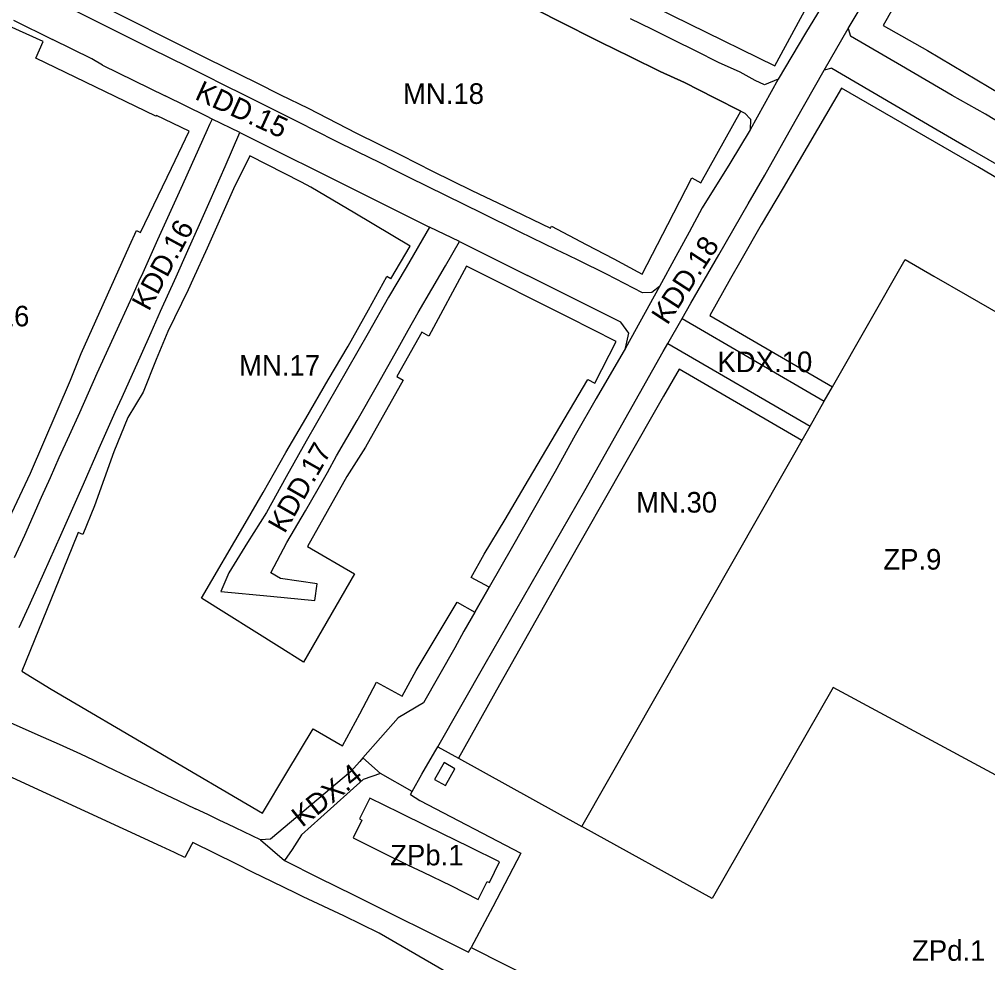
# Model space of a CAD drawing. Extents: x 7425067 to 7426806, y 5549054 to 5550619.
# Drawn here: x 7425775.6 to 7426010.9, y 5549627.2 to 5549856.3 of the extents above; entities that cross this region are included whole.
import ezdxf

# ---------------------------------------------------------------- set-up
doc = ezdxf.new("R2010")
doc.units = 0
for name, color, linetype in [('LIN_Linia Zabudowy Nieprzekraczalna', 7, 'Continuous'), ('LIN_linia zabudowy obowiązująca', 7, 'Continuous'), ('LIN_linie_rozgraniczajace', 7, 'Continuous'), ('TXT_Oznaczenia_przeznaczen', 7, 'Continuous')]:
    doc.layers.add(name, color=color, linetype=linetype)

msp = doc.modelspace()

# ---------------------------------------------------------------- linework, layer by layer
at = {"layer": 'LIN_Linia Zabudowy Nieprzekraczalna'}
for points in [[(7425801.8723, 5549907.3701), (7425781.18, 5549867.15), (7425792.69, 5549861.24), (7425821.44, 5549846.75), (7425833.18, 5549840.94), (7425839.1, 5549837.99), (7425845.79, 5549834.72), (7425857.5, 5549828.65), (7425868.39, 5549823.29), (7425875.97, 5549819.39), (7425885.52, 5549814.72), (7425893.57, 5549810.92), (7425904.63, 5549805.55), (7425904.8856, 5549806.0772)], [(7426012.3076, 5549902.588), (7426006.73, 5549891.48), (7426000.31, 5549880.37), (7425992.85, 5549867.81), (7425985.5251, 5549854.844)], [(7425845.48, 5549901.28), (7425878.63, 5549884.56), (7425896.7396, 5549875.6767), (7425959.1857, 5549845.0449)], [(7425937.19, 5549840.97), (7425931.34, 5549843.63), (7425924.075, 5549847.175), (7425916.81, 5549850.72), (7425913.24, 5549852.55), (7425909.79, 5549854.33), (7425899, 5549859.75), (7425891.99, 5549863.26), (7425886.51, 5549865.975), (7425881.03, 5549868.69), (7425872.94, 5549872.69), (7425868.2, 5549875.09), (7425863.46, 5549877.49), (7425859.61, 5549879.4), (7425855.92, 5549881.24), (7425845.49, 5549886.35), (7425841.62, 5549888.14), (7425836.88, 5549890.54), (7425827.51, 5549895.12), (7425821, 5549898.215)], [(7425959.1857, 5549845.0449), (7425974.23, 5549872.89), (7425980.2392, 5549884.0122)], [(7425779.596, 5549846.8457), (7425781.4, 5549850.92), (7425773.11, 5549854.61)], [(7425985.5251, 5549854.844), (7425996.26, 5549848.76), (7426104.12, 5549784.6), (7426109.41, 5549781.49), (7426114.72, 5549778.36), (7426119.83, 5549787.08), (7426121.57, 5549786.02), (7426124.86, 5549791.65), (7426129.1728, 5549798.7414)], [(7425816.85, 5549829.15), (7425808.9, 5549832.99), (7425808.8, 5549832.79), (7425798.91, 5549837.55), (7425779.596, 5549846.8457)], [(7425950.9226, 5549834.0102), (7425944.53, 5549837.25), (7425937.19, 5549840.97)], [(7425975.3407, 5549839.5758), (7425961.22, 5549815.39)], [(7426104.0355, 5549764.0477), (7426079.76, 5549778.72), (7426056.48, 5549792.16), (7426008.48, 5549820.45), (7425975.3407, 5549839.5758)], [(7425939.0202, 5549817.8337), (7425941.21, 5549816.62), (7425950.9226, 5549834.0102)], [(7425805.0375, 5549804.5658), (7425812.54, 5549820.18), (7425816.85, 5549829.15)], [(7425831.65, 5549823.14), (7425827.62, 5549815.16), (7425821.28, 5549800.69), (7425817.79, 5549793.15), (7425816.65, 5549790.6), (7425811.68, 5549780.51), (7425808.85, 5549773.71), (7425805.72, 5549765.73), (7425802, 5549759.61), (7425798.55, 5549751.25), (7425793.85, 5549738.13), (7425791.05, 5549731.22), (7425789.9, 5549731.68), (7425788.36, 5549727.88), (7425776.2423, 5549697.9792)], [(7425846.4612, 5549815.539), (7425844.16, 5549816.72), (7425831.65, 5549823.14)], [(7425926.9746, 5549794.4551), (7425933.16, 5549806.46), (7425939.0202, 5549817.8337)], [(7425870.6, 5549801.21), (7425857.14, 5549809.2), (7425846.4612, 5549815.539)], [(7425961.22, 5549815.39), (7425955.8554, 5549806.3779), (7425950.9113, 5549797.7633), (7425948.4236, 5549793.3414)], [(7425790.61, 5549775.16), (7425802.37, 5549801.26), (7425804.053, 5549804.9953)], [(7425804.053, 5549804.9953), (7425805.0375, 5549804.5658)], [(7425904.8856, 5549806.0772), (7425913.3, 5549801.65), (7425920.08, 5549798.1), (7425925.92, 5549795.01), (7425926.9746, 5549794.4551)], [(7425865.9, 5549793.29), (7425870.6, 5549801.21)], [(7425862.3827, 5549695.3324), (7425868.66, 5549691.91), (7425872.06, 5549698.16), (7425881.9787, 5549714.7182), (7425886.2468, 5549712.3147), (7425889.7427, 5549718.364), (7425885.4, 5549720.72), (7425888.56, 5549726.41), (7425893.62, 5549734.81), (7425899.34, 5549744.46), (7425913.7682, 5549768.8012), (7425915.44, 5549767.95), (7425920.59, 5549778.05), (7425909.13, 5549783.88), (7425884.29, 5549796.38), (7425875.1185, 5549779.3888), (7425873.44, 5549780.35), (7425867.32, 5549769.53), (7425868.8363, 5549768.6578)], [(7425819.8779, 5549715.7686), (7425830.51, 5549733.9), (7425834.85, 5549741.36), (7425840.32, 5549751.1), (7425845.18, 5549759.39), (7425850.65, 5549768.79), (7425855.51, 5549776.91), (7425860.42, 5549785.78), (7425864.9043, 5549793.881)], [(7425865.9, 5549793.29), (7425864.9043, 5549793.881)], [(7425948.4236, 5549793.3414), (7425943.4128, 5549784.38)], [(7425943.4128, 5549784.38), (7425973.1723, 5549767.0611), (7425973.2096, 5549767.0394)], [(7425778.34, 5549746.1), (7425788.05, 5549768.68), (7425790.61, 5549775.16)], [(7425935.9261, 5549771.3818), (7425932.134, 5549764.7805), (7425922.6414, 5549748.1635), (7425908.1791, 5549722.7371), (7425892.3082, 5549694.6631), (7425882.3094, 5549676.8667)], [(7425965.702, 5549754.0532), (7425935.9261, 5549771.3818)], [(7425868.8363, 5549768.6578), (7425859.69, 5549752.4), (7425855.17, 5549745.29), (7425845.6179, 5549728.2498), (7425857.0337, 5549721.6548)], [(7425770.46, 5549726.57), (7425773.16, 5549732.55), (7425772.25, 5549732.96), (7425773.82, 5549736.43), (7425778.34, 5549746.1)], [(7425857.0337, 5549721.6548), (7425844.6486, 5549700.2175)], [(7425844.6486, 5549700.2175), (7425838.75, 5549703.92), (7425819.8779, 5549715.7686)], [(7425776.2423, 5549697.9792), (7425783.38, 5549693.62), (7425834.66, 5549663.52), (7425840.64, 5549673.42), (7425847.016, 5549683.9755)], [(7425847.016, 5549683.9755), (7425854.16, 5549679.9), (7425858.3, 5549687.67), (7425862.3827, 5549695.3324)]]:
    msp.add_lwpolyline(points, dxfattribs=at)
at = {"layer": 'LIN_linia zabudowy obowiązująca'}
for points in [[(7425876.5, 5549671.7), (7425879.15, 5549670.22), (7425881.45, 5549674.24), (7425878.85, 5549675.78), (7425876.5, 5549671.7)], [(7425860.77, 5549667.17), (7425858.29, 5549662.13), (7425858.81, 5549661.84), (7425856.69, 5549657.56), (7425863.4, 5549654.24), (7425870.12, 5549650.91), (7425873.69, 5549649.16), (7425880.44, 5549645.92), (7425887.11, 5549642.58), (7425889.28, 5549646.92), (7425889.8273, 5549646.6486), (7425892.29, 5549651.68), (7425885.04, 5549655.24), (7425878.26, 5549658.58), (7425874.76, 5549660.29), (7425868.02, 5549663.6), (7425860.77, 5549667.17)]]:
    msp.add_lwpolyline(points, dxfattribs=at)
at = {"layer": 'LIN_linie_rozgraniczajace'}
for points in [[(7425973.38, 5549864.05), (7425966.665, 5549852.915)], [(7425977.03, 5549854.05), (7425983.91, 5549865.66)], [(7425798.71, 5549853.58), (7425787.855, 5549859.015)], [(7425899, 5549859.75), (7425909.79, 5549854.33)], [(7425774.16, 5549856.13), (7425783.69, 5549851.43)], [(7425909.79, 5549854.33), (7425913.24, 5549852.55)], [(7425929.25, 5549853.88), (7425924.14, 5549856.46)], [(7425807.635, 5549849.165), (7425798.71, 5549853.58)], [(7425913.24, 5549852.55), (7425916.81, 5549850.72)], [(7425934.64, 5549851.23), (7425929.25, 5549853.88)], [(7425966.665, 5549852.915), (7425959.95, 5549841.78)], [(7425971.2, 5549843.94), (7425977.03, 5549854.05)], [(7425977.03, 5549854.05), (7425977.56, 5549852.24)], [(7425989.925, 5549845.03), (7425977.56, 5549852.24)], [(7425793.22, 5549846.73), (7425783.69, 5549851.43)], [(7425916.81, 5549850.72), (7425924.075, 5549847.175)], [(7425940.08, 5549848.55), (7425934.64, 5549851.23)], [(7425816.56, 5549844.75), (7425807.635, 5549849.165)], [(7425945.48, 5549845.85), (7425940.08, 5549848.55)], [(7425795.84, 5549845.16), (7425793.22, 5549846.73)], [(7425795.84, 5549845.16), (7425803.45, 5549841.455)], [(7425924.075, 5549847.175), (7425931.34, 5549843.63)], [(7425950.75, 5549843.44), (7425945.48, 5549845.85)], [(7426002.29, 5549837.82), (7425989.925, 5549845.03)], [(7425820.72, 5549842.66), (7425816.56, 5549844.75)], [(7425825.52, 5549840.24), (7425820.72, 5549842.66)], [(7425931.34, 5549843.63), (7425937.19, 5549840.97)], [(7425956.68, 5549840.39), (7425954.39, 5549841.47), (7425950.75, 5549843.44)], [(7425964.09, 5549831.58), (7425971.2, 5549843.94)], [(7425973.02, 5549844.45), (7425971.2, 5549843.94)], [(7425973.02, 5549844.45), (7425985.32, 5549837.24)], [(7425803.45, 5549841.455), (7425811.06, 5549837.75)], [(7425830.03, 5549838.02), (7425825.52, 5549840.24)], [(7425937.19, 5549840.97), (7425944.53, 5549837.25)], [(7425959.95, 5549841.78), (7425953.2, 5549829.44)], [(7425959.95, 5549841.78), (7425956.68, 5549840.39)], [(7425834.54, 5549835.8), (7425830.03, 5549838.02)], [(7426010.36, 5549833.25), (7426002.29, 5549837.82)], [(7425821.12, 5549832.75), (7425811.06, 5549837.75)], [(7425843.44, 5549831.315), (7425834.54, 5549835.8)], [(7425944.53, 5549837.25), (7425950.9226, 5549834.0102), (7425951.87, 5549833.53)], [(7425985.32, 5549837.24), (7425997.62, 5549830.03)], [(7425951.87, 5549833.53), (7425953.24, 5549832.09)], [(7426018.22, 5549828.5), (7426010.36, 5549833.25)], [(7425822.44, 5549832.09), (7425821.12, 5549832.75)], [(7425821.85, 5549830.78), (7425821.26, 5549829.47)], [(7425822.44, 5549832.09), (7425821.85, 5549830.78)], [(7425829.21, 5549828.84), (7425822.44, 5549832.09)], [(7425852.34, 5549826.83), (7425843.44, 5549831.315)], [(7425953.24, 5549832.09), (7425953.2, 5549829.44)], [(7425956.71, 5549818.43), (7425964.09, 5549831.58)], [(7425821.26, 5549829.47), (7425815.23, 5549816.11)], [(7425825.58, 5549820.56), (7425829.21, 5549828.84)], [(7425829.21, 5549828.84), (7425839.51, 5549823.65)], [(7425953.2, 5549829.44), (7425948.24, 5549821.29)], [(7425997.62, 5549830.03), (7426005.595, 5549825.4)], [(7425857.79, 5549824.13), (7425852.34, 5549826.83)], [(7425863.24, 5549821.43), (7425857.79, 5549824.13)], [(7426005.595, 5549825.4), (7426013.57, 5549820.77)], [(7425839.51, 5549823.65), (7425848.05, 5549819.39)], [(7425866.78, 5549819.68), (7425863.24, 5549821.43)], [(7425821.95, 5549812.28), (7425825.58, 5549820.56)], [(7425848.05, 5549819.39), (7425861.67, 5549812.625)], [(7425870.32, 5549817.93), (7425866.78, 5549819.68)], [(7425948.24, 5549821.29), (7425941.55, 5549810.5)], [(7425879.22, 5549813.52), (7425870.32, 5549817.93)], [(7425952.68, 5549811.49), (7425956.71, 5549818.43)], [(7425815.23, 5549816.11), (7425809.2, 5549802.75)], [(7425820.685, 5549809.38), (7425821.95, 5549812.28)], [(7425861.67, 5549812.625), (7425875.29, 5549805.86)], [(7425888.12, 5549809.11), (7425879.22, 5549813.52)], [(7425941.55, 5549810.5), (7425938.335, 5549804.605)], [(7425945.56, 5549799.13), (7425952.68, 5549811.49)], [(7425819.42, 5549806.48), (7425820.685, 5549809.38)], [(7425897.14, 5549804.735), (7425888.12, 5549809.11)], [(7425816.56, 5549800.13), (7425819.42, 5549806.48)], [(7425875.29, 5549805.86), (7425869.57, 5549796.05)], [(7425882.56, 5549802.32), (7425875.29, 5549805.86)], [(7425809.2, 5549802.75), (7425805.26, 5549794.05)], [(7425906.16, 5549800.36), (7425897.14, 5549804.735)], [(7425938.335, 5549804.605), (7425935.12, 5549798.71)], [(7425879.14, 5549796.44), (7425882.56, 5549802.32)], [(7425882.56, 5549802.32), (7425887.895, 5549799.665)], [(7425908.84, 5549799.055), (7425906.16, 5549800.36)], [(7425813.7, 5549793.78), (7425816.56, 5549800.13)], [(7425887.895, 5549799.665), (7425893.23, 5549797.01)], [(7425911.52, 5549797.75), (7425908.84, 5549799.055)], [(7425935.12, 5549798.71), (7425931.14, 5549791.4)], [(7425938.79, 5549787.38), (7425945.56, 5549799.13)], [(7425971.1902, 5549763.5865), (7425973.1723, 5549767.0611), (7425990.8296, 5549798.0135)], [(7425990.8296, 5549798.0135), (7425997.84, 5549793.92)], [(7425869.57, 5549796.05), (7425865.34, 5549788.79)], [(7425875.84, 5549790.765), (7425879.14, 5549796.44)], [(7425893.23, 5549797.01), (7425899.07, 5549794.1)], [(7425918.31, 5549794.43), (7425911.52, 5549797.75)], [(7425804.99, 5549793.43), (7425802.95, 5549788.85)], [(7425805.26, 5549794.05), (7425804.99, 5549793.43)], [(7425809.94, 5549785.45), (7425813.7, 5549793.78)], [(7425904.91, 5549791.19), (7425899.07, 5549794.1)], [(7425927.04, 5549789.87), (7425918.31, 5549794.43)], [(7425997.84, 5549793.92), (7426005.99, 5549789.25)], [(7425872.54, 5549785.09), (7425875.84, 5549790.765)], [(7425921.75, 5549782.75), (7425904.91, 5549791.19)], [(7425931.14, 5549791.4), (7425922.91, 5549776.46)], [(7425931.14, 5549791.4), (7425929.31, 5549789.98)], [(7425802.95, 5549788.85), (7425800.27, 5549783)], [(7425865.34, 5549788.79), (7425860.335, 5549780.075)], [(7425929.31, 5549789.98), (7425927.04, 5549789.87)], [(7426005.99, 5549789.25), (7426014.04, 5549784.65)], [(7425933.1648, 5549777.6169), (7425936.6594, 5549783.6822), (7425938.79, 5549787.38)], [(7425807.625, 5549780.21), (7425809.94, 5549785.45)], [(7425870.08, 5549780.775), (7425872.54, 5549785.09)], [(7425800.27, 5549783), (7425794.47, 5549770.27)], [(7425923.7, 5549780.1), (7425921.75, 5549782.75)], [(7425936.6594, 5549783.6822), (7425971.1902, 5549763.5865)], [(7425805.31, 5549774.97), (7425807.625, 5549780.21)], [(7425860.335, 5549780.075), (7425855.33, 5549771.36)], [(7425867.62, 5549776.46), (7425870.08, 5549780.775)], [(7425922.91, 5549776.46), (7425923.7, 5549780.1)], [(7425932.02, 5549775.63), (7425933.1648, 5549777.6169)], [(7425933.1648, 5549777.6169), (7425967.7215, 5549757.506)], [(7425800.57, 5549764.53), (7425805.31, 5549774.97)], [(7425865.135, 5549772.005), (7425867.62, 5549776.46)], [(7425912.98, 5549741.85), (7425932.02, 5549775.63)], [(7425922.91, 5549776.46), (7425915.79, 5549764.24)], [(7425862.65, 5549767.55), (7425865.135, 5549772.005)], [(7425794.47, 5549770.27), (7425790.21, 5549760.76)], [(7425855.33, 5549771.36), (7425850.315, 5549762.61)], [(7425857.67, 5549758.915), (7425862.65, 5549767.55)], [(7425798.86, 5549760.93), (7425800.57, 5549764.53)], [(7425850.315, 5549762.61), (7425845.3, 5549753.86)], [(7425915.79, 5549764.24), (7425910.7, 5549755.33)], [(7425912.2581, 5549660.2816), (7425967.7215, 5549757.506), (7425971.1902, 5549763.5865)], [(7425790.21, 5549760.76), (7425787.71, 5549755.23)], [(7425795.035, 5549752.16), (7425798.86, 5549760.93)], [(7425852.69, 5549750.28), (7425857.67, 5549758.915)], [(7425787.71, 5549755.23), (7425785.24, 5549749.78)], [(7425845.3, 5549753.86), (7425840.47, 5549745.195)], [(7425910.7, 5549755.33), (7425905.79, 5549746.53)], [(7425791.21, 5549743.39), (7425795.035, 5549752.16)], [(7425785.24, 5549749.78), (7425783.08, 5549744.97)], [(7425850.45, 5549746.28), (7425852.69, 5549750.28)], [(7425848.21, 5549742.28), (7425850.45, 5549746.28)], [(7425905.79, 5549746.53), (7425895.45, 5549728.24)], [(7425783.08, 5549744.97), (7425780.92, 5549740.16)], [(7425840.47, 5549745.195), (7425835.64, 5549736.53)], [(7425785.705, 5549731.065), (7425791.21, 5549743.39)], [(7425846.665, 5549739.62), (7425848.21, 5549742.28)], [(7425888.83, 5549699.82), (7425912.98, 5549741.85)], [(7425780.92, 5549740.16), (7425778.885, 5549735.545)], [(7425845.12, 5549736.96), (7425846.665, 5549739.62)], [(7425840.61, 5549729.27), (7425845.12, 5549736.96)], [(7425778.885, 5549735.545), (7425776.85, 5549730.93)], [(7425835.64, 5549736.53), (7425831.075, 5549729.22)], [(7425776.85, 5549730.93), (7425774.32, 5549725.54)], [(7425780.2, 5549718.74), (7425785.705, 5549731.065)], [(7425831.075, 5549729.22), (7425826.51, 5549721.91)], [(7425836.72, 5549721.85), (7425840.61, 5549729.27)], [(7425895.45, 5549728.24), (7425889.7427, 5549718.364), (7425886.2468, 5549712.3147), (7425883.58, 5549707.7)], [(7425826.51, 5549721.91), (7425824.57, 5549717.31)], [(7425839.09, 5549720.52), (7425836.72, 5549721.85)], [(7425847.98, 5549719.18), (7425839.09, 5549720.52)], [(7425777.89, 5549713.675), (7425780.2, 5549718.74)], [(7425847.41, 5549715.16), (7425847.98, 5549719.18)], [(7425824.57, 5549717.31), (7425836.61, 5549716.175)], [(7425836.61, 5549716.175), (7425847.41, 5549715.16)], [(7425775.58, 5549708.61), (7425777.89, 5549713.675)], [(7425883.58, 5549707.7), (7425881.46, 5549703.65)], [(7425881.46, 5549703.65), (7425873.84, 5549690.32)], [(7425876.56, 5549678.43), (7425877.2655, 5549679.6599), (7425888.83, 5549699.82)], [(7425973.3638, 5549694.0133), (7425943.9187, 5549642.7486)], [(7426045.0272, 5549655.3976), (7425973.3638, 5549694.0133)], [(7425873.84, 5549690.32), (7425867.65, 5549686.63)], [(7425777.07, 5549683.86), (7425773.61, 5549685.4)], [(7425867.65, 5549686.63), (7425859.095, 5549676.977), (7425858.3116, 5549676.0932)], [(7425780.2, 5549682.47), (7425777.07, 5549683.86)], [(7425785.365, 5549680.17), (7425780.2, 5549682.47)], [(7425790.53, 5549677.87), (7425785.365, 5549680.17)], [(7425793.66, 5549676.375), (7425790.53, 5549677.87)], [(7425873.41, 5549672.95), (7425876.56, 5549678.43)], [(7425877.2655, 5549679.6599), (7425882.3094, 5549676.8667), (7425912.2581, 5549660.2816)], [(7425796.79, 5549674.88), (7425793.66, 5549676.375)], [(7425858.3116, 5549676.0932), (7425856.04, 5549673.53)], [(7425863.3893, 5549673.1712), (7425859.095, 5549676.977)], [(7425802.575, 5549672.125), (7425796.79, 5549674.88)], [(7425856.04, 5549673.53), (7425836.66, 5549657.23)], [(7425863.3893, 5549673.1712), (7425859.12, 5549671.68)], [(7425871.02, 5549668.78), (7425863.3893, 5549673.1712)], [(7425810.13, 5549655.38), (7425772.86, 5549672.55)], [(7425808.36, 5549669.37), (7425802.575, 5549672.125)], [(7425859.12, 5549671.68), (7425848.89, 5549662.5)], [(7425871.02, 5549668.78), (7425873.41, 5549672.95)], [(7425808.36, 5549669.37), (7425814.23, 5549666.57)], [(7425870.66, 5549668.07), (7425871.02, 5549668.78)], [(7425814.23, 5549666.57), (7425818.4, 5549664.59)], [(7425870.66, 5549668.07), (7425872.9, 5549666.58)], [(7425872.9, 5549666.58), (7425897.49, 5549653.78)], [(7425821.38, 5549663.17), (7425818.4, 5549664.59)], [(7425824.36, 5549661.75), (7425821.38, 5549663.17)], [(7425826.25, 5549660.845), (7425824.36, 5549661.75)], [(7425848.89, 5549662.5), (7425844.18, 5549658.28)], [(7425828.14, 5549659.94), (7425826.25, 5549660.845)], [(7425834.24, 5549657.03), (7425828.14, 5549659.94)], [(7425943.9187, 5549642.7486), (7425912.2581, 5549660.2816)], [(7425836.66, 5549657.23), (7425834.24, 5549657.03)], [(7425834.24, 5549657.03), (7425840, 5549651.98)], [(7425844.18, 5549658.28), (7425841.86, 5549654.71)], [(7425813.31, 5549653.92), (7425810.13, 5549655.38)], [(7425817.43, 5549655.84), (7425815.83, 5549652.76)], [(7425817.73, 5549656.4), (7425817.43, 5549655.84)], [(7425828.49, 5549651.09), (7425817.73, 5549656.4)], [(7425841.86, 5549654.71), (7425840, 5549651.98)], [(7425813.45, 5549653.85), (7425813.31, 5549653.92)], [(7425815.83, 5549652.76), (7425813.45, 5549653.85)], [(7425840, 5549651.98), (7425848.395, 5549647.825)], [(7425897.49, 5549653.78), (7425890.66, 5549640.78)], [(7425832.29, 5549649.22), (7425828.49, 5549651.09)], [(7425837.13, 5549646.84), (7425832.29, 5549649.22)], [(7425848.395, 5549647.825), (7425856.79, 5549643.67)], [(7425842.79, 5549644.05), (7425837.13, 5549646.84)], [(7425844.57, 5549643.18), (7425842.79, 5549644.05)], [(7425854.43, 5549638.6), (7425844.57, 5549643.18)], [(7425856.79, 5549643.67), (7425884.76, 5549629.77)], [(7425890.66, 5549640.78), (7425885.4, 5549630.87)], [(7425863.02, 5549634.35), (7425854.43, 5549638.6)], [(7425881.34, 5549623.75), (7425863.02, 5549634.35)], [(7425884.76, 5549629.77), (7425885.4, 5549630.87)], [(7425885.4, 5549630.87), (7425901.77, 5549622.65)]]:
    msp.add_lwpolyline(points, dxfattribs=at)

# ---------------------------------------------------------------- texts
at = {"layer": 'TXT_Oznaczenia_przeznaczen'}
for s, rotation, p in [('KDD.15', 335.481366, (7425818.0022, 5549837.0286)), ('KDD.16', 61.625473, (7425807.0675, 5549785.2172)), ('KDD.18', 56.919657, (7425933.0612, 5549781.8552)), ('KDD.17', 60.359628, (7425840.0805, 5549731.2251)), ('KDX.4', 38.670763, (7425844.3215, 5549659.9179))]:
    msp.add_text(s, height=5, rotation=rotation, dxfattribs=at).set_placement(p)
for s, p in [('MN.18', (7425868.821, 5549835.763)), ('MN.16', (7425758.3535, 5549781.7422)), ('MN.17', (7425828.9873, 5549769.75)), ('KDX.10', (7425945.2325, 5549770.6249)), ('MN.30', (7425925.4557, 5549736.5131)), ('ZP.9', (7425985.5324, 5549722.6655)), ('ZPb.1', (7425865.707, 5549650.8208)), ('ZPd.1', (7425992.4956, 5549627.6615))]:
    msp.add_text(s, height=5, dxfattribs=at).set_placement(p)

doc.saveas('drawing.dxf')
